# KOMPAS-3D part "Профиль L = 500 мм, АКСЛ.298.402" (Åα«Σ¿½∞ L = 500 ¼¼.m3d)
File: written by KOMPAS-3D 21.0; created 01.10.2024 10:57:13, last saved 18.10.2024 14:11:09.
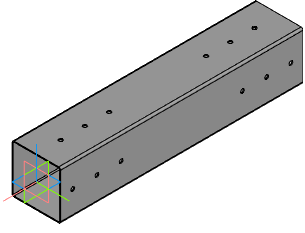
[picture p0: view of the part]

Document properties: Полное имя файла: C:\Users\Алексей Бочаров\YandexDisk\Соединения бруса\Соединения бруса\КВАТРО\Профиль L = 500 мм.m3d; Автор: Алексей Бочаров

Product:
- Part/product: Профиль L = 500 мм  | designation АКСЛ.298.402
    Масса: 3.029613
    Форматы листов документа: A3

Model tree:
1. Эскиз:1
2. Элемент выдавливания:1
     Расстояние 2 = 500
3. Эскиз:3  (with: Элемент выдавливания:1)
4. Элемент выдавливания:3  (with: Элемент выдавливания:1)
     Расстояние 2 = 2
5. Эскиз:4  (with: Элемент выдавливания:1)
6. Элемент выдавливания:4  (with: Элемент выдавливания:1)
     Расстояние 2 = 2

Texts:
  АКСЛ.298.402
